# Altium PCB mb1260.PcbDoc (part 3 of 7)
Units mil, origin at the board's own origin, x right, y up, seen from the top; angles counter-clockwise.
Board outline 3189.01 x 3818.89 mil, 6 copper layers (TOP, L2_GND, L3_VCC, L4_SIG, L5_GND, BOTTOM), stack 62.2 mil thick; 308 components, 287 nets, 1220 pads, 851 vias.
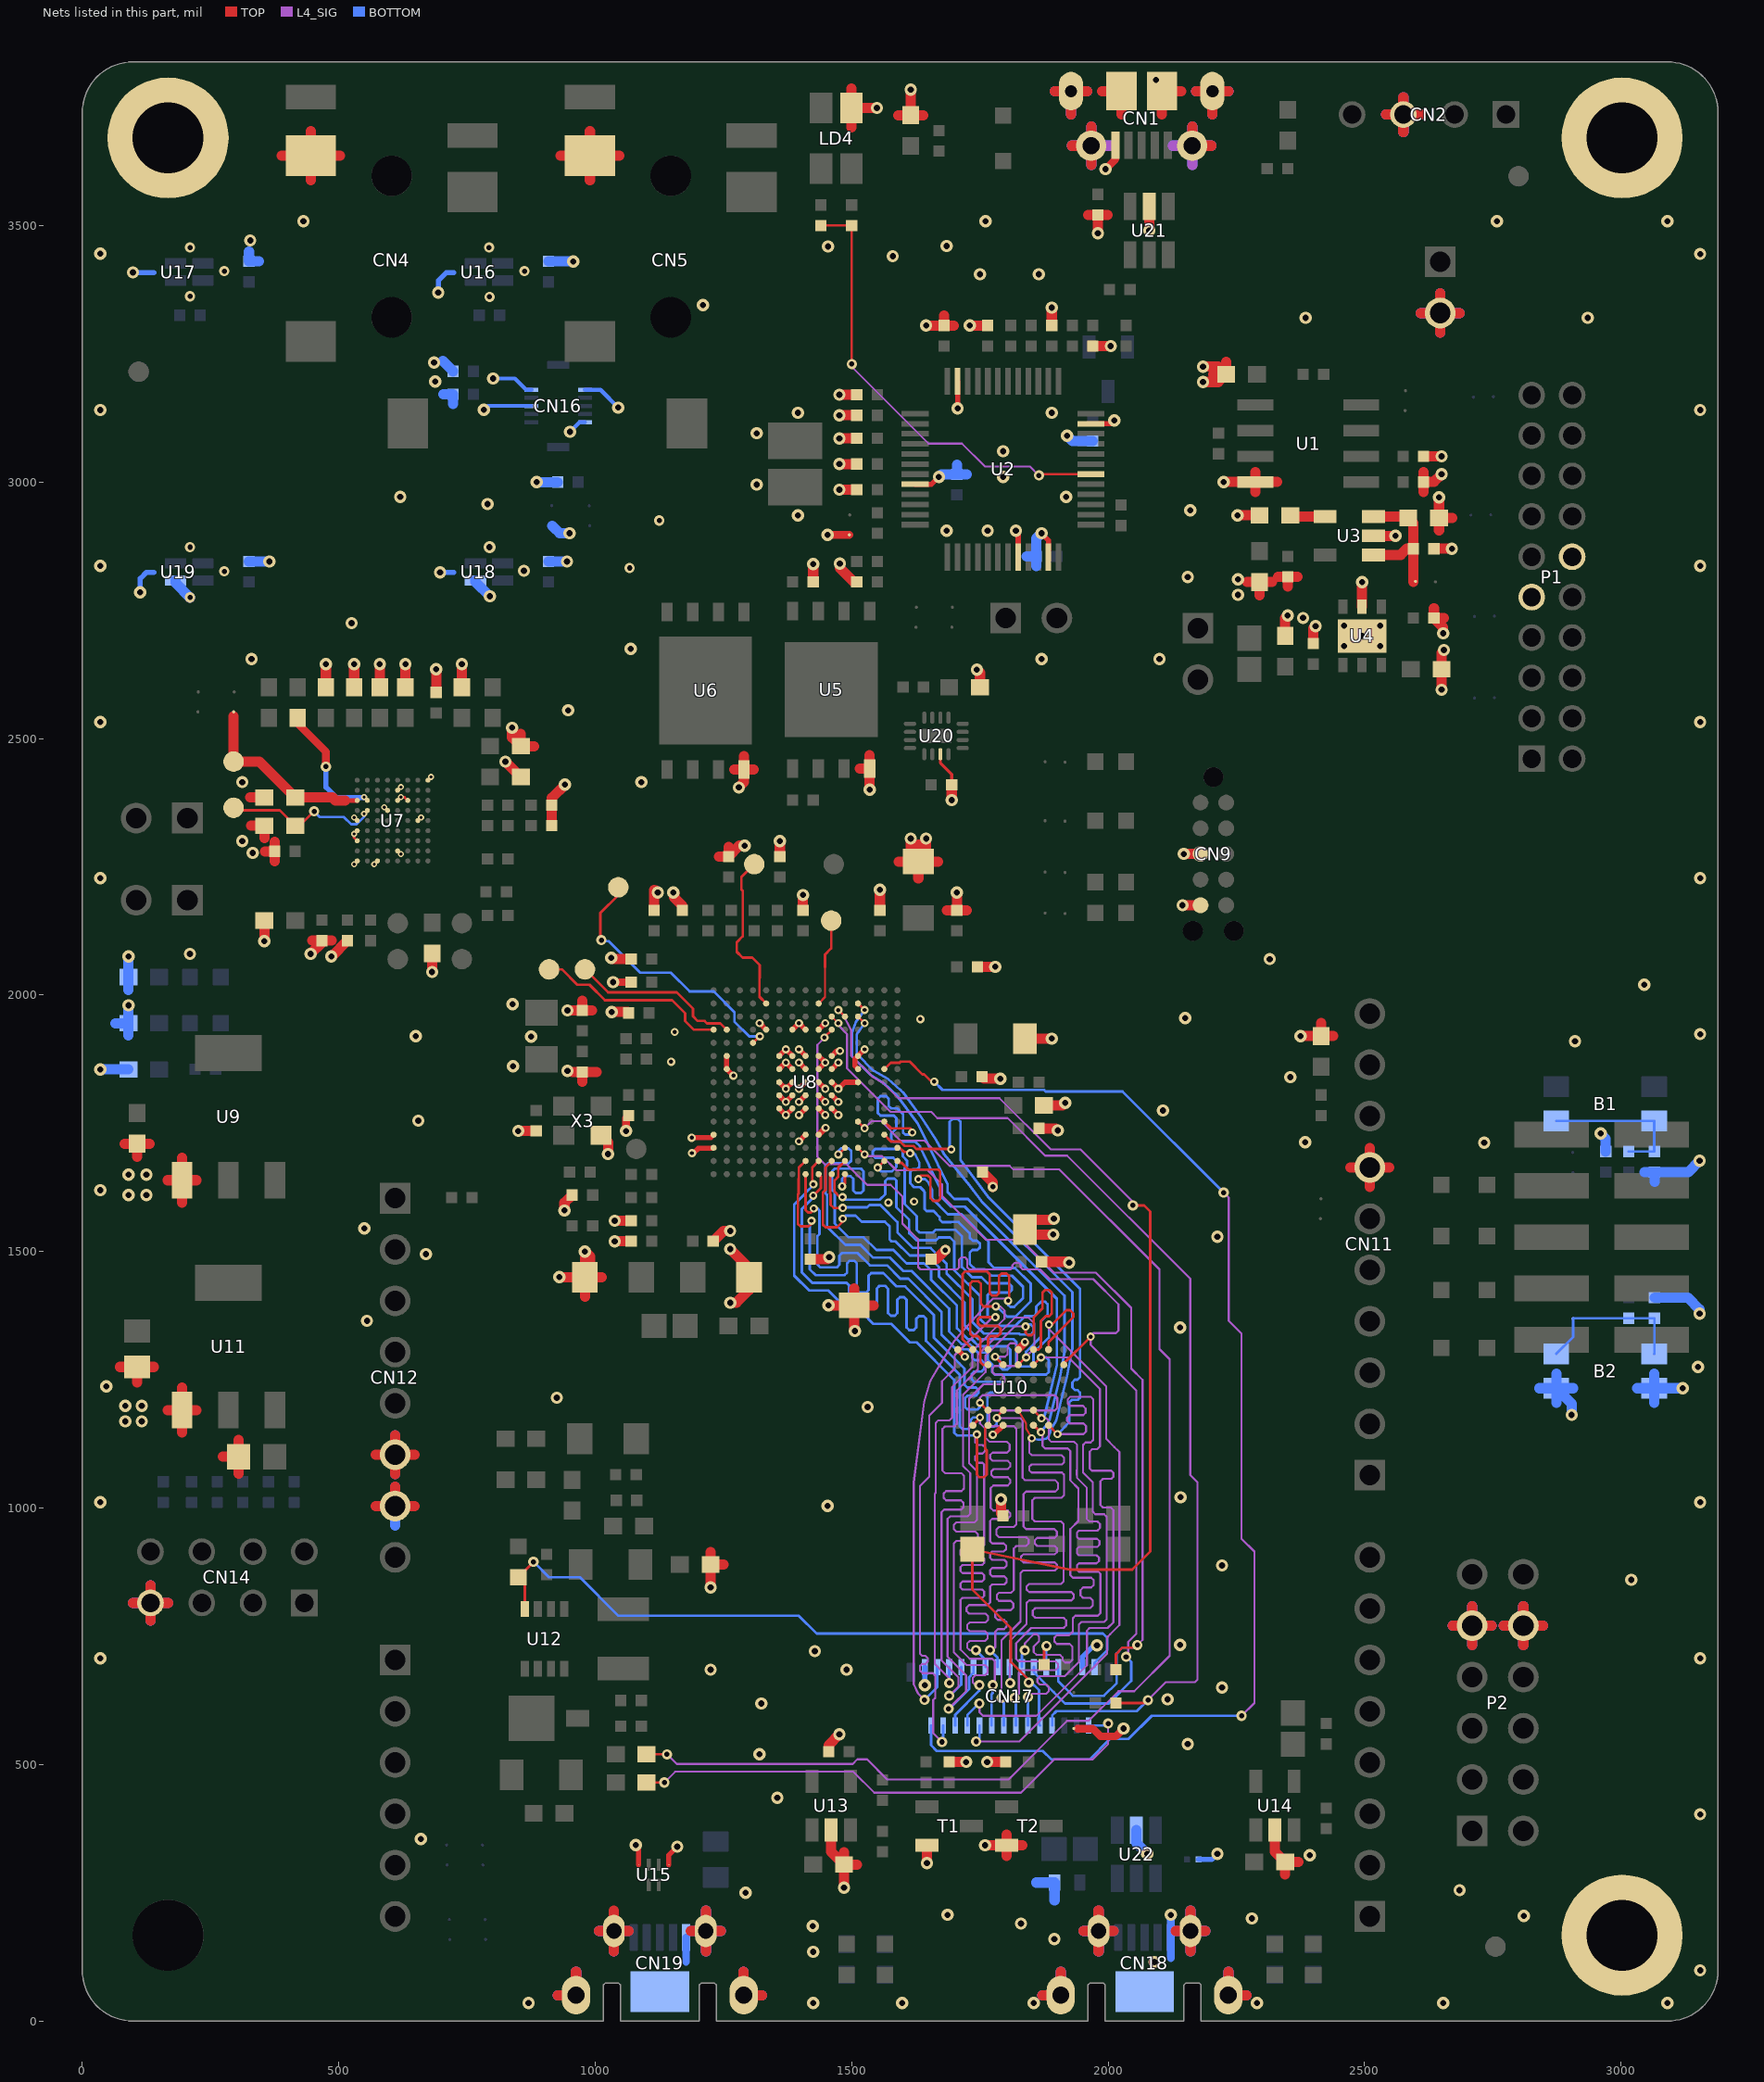
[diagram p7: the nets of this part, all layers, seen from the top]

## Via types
v1: diameter 24, hole 12, TOP to BOTTOM, tented both sides, 389 vias
v2: diameter 20, hole 10, TOP to BOTTOM, tented both sides, 231 vias
v3: diameter 16, hole 8, TOP to BOTTOM, tented both sides, 196 vias
v4: diameter 12, hole 6, TOP to BOTTOM, tented both sides, 35 vias

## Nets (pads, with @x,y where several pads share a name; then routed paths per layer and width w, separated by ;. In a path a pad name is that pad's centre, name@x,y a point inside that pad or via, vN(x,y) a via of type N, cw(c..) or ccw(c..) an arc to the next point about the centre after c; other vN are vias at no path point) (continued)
GND: B2.2 B2.4 C1.2 C2.2 C3.1 C4.1 C5.1 C6.1 C7.1 C8.1 C9.1 C10.1 C11.1 C12.1 C13.1 C14.1 C15.1 C16.1 C17.1 C19.1 C20.2 C21.2 C22.2 C23.2 C24.2 C26.2 C28.2 C29.1 C31.1 C33.2 C34.2 C35.1 C36.1 C37.1 C38.1 C39.1 C40.1 C41.2 C42.2 C43.1 C44.1 C45.1 C46.1 C47.1 C48.1 C49.1 C50.1 C51.1 C52.1 C53.1 C54.2 C55.1 C56.1 C57.1 C58.1 C59.1 C60.1 C61.1 C62.1 C63.1 C64.2 C65.2 C66.2 C68.1 C71.1 C74.1 C77.2 C78.2 C79.2 C80.2 C81.1 C82.1 C83.1 C84.2 C85.2 C86.1 C87.1 C92.2 C93.1 CN1.5 CN1.6 CN1.7 CN1.8 CN1.9 CN1.10 CN1.11 CN2.3 CN3.2 CN4.3 CN5.3 CN9.3 CN9.5 CN11.7 CN12.6 CN12.7 CN14.7 CN16.1 CN16.3 CN16.6 CN16.10 CN17.1 CN17.27 CN18.5 CN18.6 CN18.7 CN18.8 CN18.9 CN18.10 CN19.5 CN19.6 CN19.7 CN19.8 CN19.9 CN19.10 H1.1 H2.1 H4.1 L5.1 LD1.2 LD2.2 LD4.1 LD5.2 LD6.2 P1.5 P1.16 P2.5 P2.11 R3.1 R6.1 R8.1 R9.1 R16.1 R17.1 R18.1 R19.1 R21.1 R22.2 R26.1 R29.1 R31.2 R33.2 R36.1 R37.1 R54.2 R61.1 R75.2 R76.1 R89.1 SB2.2 SB6.1 SB16.1 T1.2 T2.2 U1.4 U2.8 U2.20 U2.23 U2.35 U2.47 U3.2 U4.2 U4.7 U5.4 U6.4 U7.A1 U7.A3 U7.A4 U7.A5 U7.C1 U7.D6 U7.E2 U7.E7 U7.E8 U7.F7 U7.G5 U7.H9 U8.D5 U8.D7 U8.D8 U8.D9 U8.F2 U8.F6 U8.F7 U8.F8 U8.F9 U8.F10 U8.F12 U8.G2 U8.G6 U8.G7 U8.G8 U8.G9 U8.G10 U8.G12 U8.H6 U8.H7 U8.H8 U8.H9 U8.H10 U8.H12 U8.J6 U8.J7 U8.J8 U8.J9 U8.J10 U8.K6 U8.K7 U8.K8 U8.K9 U8.K10 U8.M1 U8.M8 U8.M9 U8.N1 U9.1 U10.D1 U10.E6 U10.H1 U11.1 U13.2 U14.2 U15.5 U15.8 U16.5 U17.5 U18.2 U18.5 U19.2 U19.5 U20.11 U21.2 U22.2 U23.2 U24.2 X3.2 | length 17260.3
  TOP w5: v4(529.8,2254.96) U7.A1@536.1,2261.26 ; v4(529.8,2346.3) U7.A5@536.1,2340 ; U7.A3@536.1,2300.63 529.8,2306.93 v4(529.8,2314.01) U7.A4@536.1,2320.31 ; v4(569.17,2254.96) U7.C1@575.47,2261.26 ; v4(588.86,2365.99) U7.D6@595.16,2359.69 ; U7.E2@614.84,2280.94 v4(621.14,2274.64) ; U7.E7@614.84,2379.37 v4(621.14,2385.68) 628.22,2385.68 U7.F7@634.53,2379.37 ; U7.E8@614.84,2399.06 v4(621.14,2405.36) ; U7.G5@654.21,2340 v4(660.51,2346.3) ; U7.H9@673.9,2418.74 v4(680.2,2425.04)
  TOP w6: U20.11@1672.87,2469.38 1672.87,2452.13 1695,2430 R29.1@1695,2410
  TOP w10: v1(1079,343) 1084.47,337.53 U15.8@1084.47,304.69 ; U15.5@1143.53,304.69 1143.53,323.53 v1(1160,340) ; v3(1188,1721.87) 1225.1,1721.87 U8.M1@1230.87,1727.64 ; v3(1188.63,1691.87) 1191.87,1691.87 1201,1701 1229.82,1701 U8.N1@1230.87,1702.05 ; U8.F2@1256.46,1881.18 U8.G2@1256.46,1855.59 v3(1269.32,1842.73) ; v3(1320.37,1945.22) U8.D5@1333.23,1932.36 ; U8.K6@1358.82,1778.82 1358.82,1778.69 v3(1371.55,1765.96) U8.K7@1384.41,1778.82 ; U8.J6@1358.82,1804.41 1358.82,1804.28 v3(1371.55,1791.55) U8.J7@1384.41,1804.41 ; U8.H6@1358.82,1830 1358.82,1829.87 v3(1371.55,1817.14) U8.H7@1384.41,1830 ; U8.G6@1358.82,1855.59 1358.82,1855.72 v3(1371.55,1868.45) U8.G7@1384.41,1855.59 ; U8.F6@1358.82,1881.18 1358.82,1881.31 v3(1371.55,1894.04) U8.F7@1384.41,1881.18 ; U8.D7@1384.41,1932.36 1384.41,1932.49 v3(1397.14,1945.22) U8.D8@1410,1932.36 ; v3(1397.14,1714.78) U8.M8@1410,1727.64 ; v3(1397.14,1765.96) U8.K8@1410,1778.82 ; v3(1397.14,1791.55) U8.J8@1410,1804.41 ; v3(1397.14,1817.14) U8.H8@1410,1830 ; v3(1397.14,1868.45) U8.G8@1410,1855.59 ; v3(1397.14,1894.04) U8.F8@1410,1881.18 ; U8.K9@1435.59,1778.82 v3(1448.45,1765.96) ; U8.J9@1435.59,1804.41 v3(1448.45,1791.55) ; U8.H9@1435.59,1830 v3(1448.45,1817.14) ; U8.G9@1435.59,1855.59 v3(1448.45,1868.45) 1435.72,1881.18 U8.F9@1435.59,1881.18 ; U8.D9@1435.59,1932.36 v3(1448.32,1945.09) ; U8.K10@1461.18,1778.82 v3(1474.04,1765.96) ; U8.J10@1461.18,1804.41 v3(1474.04,1791.55) ; U8.H10@1461.18,1830 v3(1474.04,1817.14) 1486.9,1830 U8.H12@1512.36,1830 ; U8.G10@1461.18,1855.59 v3(1474.04,1868.45) ; U8.F10@1461.18,1881.18 1471,1891 v3(1477,1891) ; U8.G12@1512.36,1855.59 1512.36,1855.75 1506,1862.11 1506,1874.82 U8.F12@1512.36,1881.18 v3(1525.22,1894.04) ; U2.8@1623.74,2995.47 1655.47,2995.47 v1(1670,3010) ; v1(1706.42,3143.58) U2.47@1706.42,3196.26 ; U10.H1@1706.65,1308.82 v3(1720.62,1294.85) ; v3(1775,1143) 1777.06,1143 U10.E6@1795.24,1161.18 ; v1(1820,2905) 1824.53,2900.47 U2.20@1824.53,2853.74 ; v1(1870,2900) 1883.58,2886.42 U2.23@1883.58,2853.74 ; U2.35@1966.26,3113.58 2005.74,3113.58 v1(2012.16,3120)
  TOP w12: U8.M9@1435.59,1727.64 1435.75,1727.64 v3(1449.1,1740.99)
  TOP w15: v1(1035,2025) C46.1@1070,2025 ; v1(1059.97,1735) 1059.97,1759.97 C53.1@1065,1765 ; v1(1453.01,2896.99) SB6.1@1495.33,2896.99 ; U10.D1@1824.76,1308.82 1837.6,1321.66 v3(1837.6,1323.6) ; 1940,570 1970,570 ; 1970,570.33 1970,570 ; v1(1995,3610) 2014.17,3629.17 CN1.5@2014.17,3656.49 ; v1(2030,570.33) 2014.67,555 1985,555 1970,570
  TOP w20: 73.78,1275 C68.1@106.8,1275 ; 82.78,1710 C57.1@106.8,1710 ; 98.97,815 CN14.7@132.99,815 ; 106.8,1244.48 C68.1@106.8,1275 ; 106.8,1684.48 C57.1@106.8,1710 ; 130.82,1710 C57.1@106.8,1710 ; 132.99,780.98 CN14.7@132.99,815 ; 132.99,849.02 CN14.7@132.99,815 ; 139.82,1275 C68.1@106.8,1275 ; 166.43,1190.98 U11.1@194.45,1190.98 ; 166.43,1638.98 U9.1@194.45,1638.98 ; 167.01,815 CN14.7@132.99,815 ; 194.45,1147.46 U11.1@194.45,1190.98 ; 194.45,1234.5 U11.1@194.45,1190.98 ; 194.45,1595.46 U9.1@194.45,1638.98 ; 194.45,1682.5 U9.1@194.45,1638.98 ; 222.47,1190.98 U11.1@194.45,1190.98 ; 222.47,1638.98 U9.1@194.45,1638.98 ; 274.48,1100 C74.1@305,1100 ; 305,1066.98 C74.1@305,1100 ; 305,1133.02 C74.1@305,1100 ; 327,2385 C29.1@355,2385 ; 329.48,2330 C31.1@355,2330 355,2305.98 ; v1(355,2105) C35.1@355,2145 ; 355.98,2280 C33.2@375,2280 ; 375,2260.98 C33.2@375,2280 ; 375,2299.02 C33.2@375,2280 ; 388.65,3635.98 CN4.3@445.67,3635.98 ; v1(445,2080) 467,2102 C41.2@467,2106 ; 445.67,3588.46 CN4.3@445.67,3635.98 ; 445.67,3683.5 CN4.3@445.67,3635.98 ; 447.98,2106 C41.2@467,2106 ; C19.1@475,2600 v1(475,2645) ; v1(485.5,2075) 486,2075 C42.2@517,2106 ; 486.02,2106 C41.2@467,2106 ; 502.69,3635.98 CN4.3@445.67,3635.98 ; C20.2@530,2600 v1(530,2645) ; 571.82,1003.94 CN12.7@609.84,1003.94 ; 571.82,1103.94 CN12.6@609.84,1103.94 ; C21.2@580,2600 v1(580,2645) ; 609.84,1041.96 CN12.7@609.84,1003.94 ; 609.84,1065.92 CN12.6@609.84,1103.94 ; 609.84,1141.96 CN12.6@609.84,1103.94 ; C22.2@630,2600 v1(630,2645) ; 647.86,1003.94 CN12.7@609.84,1003.94 ; 647.86,1103.94 CN12.6@609.84,1103.94 ; v1(682,2045) C43.1@682,2081 ; C23.2@690,2590 v1(690,2635) ; C24.2@740,2600 v1(740,2645) ; v1(825,2455) C28.2@855,2425 ; v1(838,2521) 838,2502 C26.2@855,2485 ; v1(850,1735) C55.1@885,1735 ; 855,2509.02 C26.2@855,2485 ; 880.52,2485 C26.2@855,2485 ; R33.2@915,2330 R31.2@915,2370 915,2384 v1(941,2410) ; 927.07,50.4 CN19.9@962.59,50.4 962.59,95.92 ; v1(930,1450) C64.2@980,1450 ; 932.66,3635.98 CN5.3@989.68,3635.98 ; v1(940,1580) 940,1595 C93.1@955,1610 ; v1(946,1970) C48.1@975,1970 ; v1@955.98,1850 C51.1@975,1850 ; 975,1830.98 C51.1@975,1850 ; 975,1989.02 C48.1@975,1970 ; 980,1411.98 C64.2@980,1450 ; v1@980,1488.02 C64.2@980,1450 ; v1(980,1500) 990,1490 990,1460 C64.2@980,1450 ; 989.68,3588.46 CN5.3@989.68,3635.98 ; 989.68,3683.5 CN5.3@989.68,3635.98 ; 994.02,1970 C48.1@975,1970 ; 1003,1850 C51.1@975,1850 ; 1007.39,175.6 CN19.6@1036.41,175.6 ; X3.2@1011.42,1726.46 1025,1712.88 v1(1025,1690) ; 1013.02,1450 C64.2@980,1450 ; v1(1030.96,2072.48) 1031.98,2072.48 1034.46,2070 C44.1@1070,2070 ; v1(1031.98,1967) 1063,1967 C47.1@1065,1965 ; 1036.41,136.08 CN19.6@1036.41,175.6 ; 1036.41,215.12 CN19.6@1036.41,175.6 ; v1(1038,1520) C59.1@1070,1520 ; v1(1038,1560) R61.1@1070,1560 ; 1046.7,3635.98 CN5.3@989.68,3635.98 ; 1065.43,175.6 CN19.6@1036.41,175.6 ; C36.1@1115,2165 1115,2204.41 1115.9,2203.51 1118.49,2203.51 v1(1122,2200) ; v1(1152,2200) 1154,2198 1154,2190 1170,2174 C37.1@1170,2165 ; 1186.53,175.6 CN19.7@1215.55,175.6 ; 1215.55,136.08 CN19.7@1215.55,175.6 ; 1215.55,215.12 CN19.7@1215.55,175.6 ; v1(1225,845) L5.1@1225,890 ; 1225,914.02 L5.1@1225,890 ; C60.1@1230,1520 1250,1540 v1(1263,1540) ; 1240.98,2270 R36.1@1260,2270 ; 1244.57,175.6 CN19.7@1215.55,175.6 ; 1250.52,890 L5.1@1225,890 ; 1260,2289.02 R36.1@1260,2270 ; v1(1263,1505) 1300,1468 C65.2@1300,1450 1300,1425 1275,1400 v1(1263.5,1400) ; 1270.98,2439.76 U6.4@1290,2439.76 ; v1(1280,2404.5) 1280,2405 1290,2415 U6.4@1290,2439.76 ; 1289.37,95.92 CN19.8@1289.37,50.4 1324.89,50.4 ; 1290,2465.78 U6.4@1290,2439.76 ; v1(1291.55,2291.08) 1291.47,2291.08 1291.47,2291.16 1291.31,2291.31 1281.31,2291.31 R36.1@1260,2270 ; 1309.02,2439.76 U6.4@1290,2439.76 ; R37.1@1360,2270 v1(1360,2300) ; C38.1@1405,2165 v1(1405,2195) ; C61.1@1419,1485 1452,1485 v1(1456.01,1489.01) ; C13.1@1425,2805 v1(1425,2840) ; R16.1@1455,525 1455,538 v1(1476,559) ; v1(1455,1395) C66.2@1505,1395 ; U13.2@1460,372.76 1460,330 C78.2@1485,305 ; v1(1476,2985) C7.1@1510,2985 ; v1(1476,3035) C6.1@1510,3035 ; v1(1476,3085) C4.1@1510,3085 ; v1(1476,3130) R19.1@1510,3130 ; v1(1476,3170) R17.1@1510,3170 ; v1(1477,2841) 1477,2832 1504,2805 R26.1@1510,2805 ; v1(1485,260) C78.2@1485,305 ; 1485,329.02 C78.2@1485,305 ; 1499.53,3691.54 LD4.1@1499.53,3729.06 ; 1499.53,3766.58 LD4.1@1499.53,3729.06 ; 1505,1428.02 C66.2@1505,1395 ; v1(1506,1345) 1506,1349 1505,1350 C66.2@1505,1395 ; 1510.52,305 C78.2@1485,305 ; 1515.98,2441.46 U5.4@1535,2441.46 ; v1(1535,2400) U5.4@1535,2441.46 ; 1535,2467.48 U5.4@1535,2441.46 ; 1543.02,1395 C66.2@1505,1395 ; v1(1549.06,3729.06) LD4.1@1499.53,3729.06 ; C39.1@1555,2165 v1(1555,2205) ; 1590.98,3715 LD2.2@1615,3715 ; 1591.98,2260 C34.2@1630,2260 ; v1(1615,2305) 1615,2275 C34.2@1630,2260 ; v1(1615,3765) LD2.2@1615,3715 ; 1630,2226.98 C34.2@1630,2260 ; 1630,2293.02 C34.2@1630,2260 ; 1639.02,3715 LD2.2@1615,3715 ; v1(1645,2305) 1645,2275 C34.2@1630,2260 ; v1(1645,3305) C1.2@1680,3305 ; v1(1646.69,308) T1.2@1646.69,342.6 ; C62.1@1655,1485 1665,1485 1683,1503 v2(1682.5,1503) ; 1668.02,2260 C34.2@1630,2260 ; 1680,3324.02 C1.2@1680,3305 ; 1685.98,2165 C40.1@1705,2165 ; R75.2@1690,505 v1(1723.28,505) ; v1(1695,2380) R29.1@1695,2410 ; 1699.02,3305 C1.2@1680,3305 ; v1(1705,2200) C40.1@1705,2165 ; 1724.02,2165 C40.1@1705,2165 ; v1(1730,3305) R3.1@1765,3305 ; v1(1744,2634) 1750,2628 C92.2@1750,2600 ; C45.1@1745,2055 v1(1780,2055) ; C56.1@1755,1655 1775,1635 v2(1775,1626) ; C52.1@1758.01,1836.99 v1(1790.01,1837) ; v1(1760,342.6) T2.2@1801.69,342.6 ; v1(1764,505) R76.1@1800,505 ; v1(1791,1017) 1791,989 C71.1@1795,985 ; 1801.69,322.08 T2.2@1801.69,342.6 ; 1801.69,363.12 T2.2@1801.69,342.6 ; 1832.21,342.6 T2.2@1801.69,342.6 ; C49.1@1838,1915 v1(1890,1915) ; R54.2@1865,1740 1898,1740 v1(1902,1736) ; C63.1@1870,1480 1922,1480 v1(1924,1478) ; 1871.96,50.4 CN18.9@1907.48,50.4 1907.48,95.92 ; C54.2@1875,1785 1911,1785 v1(1916,1790) ; R6.1@1890,3305 v1(1890,3340) ; v1(1893,1533) 1848,1533 C58.1@1838,1543 1838,1548 1852,1562 1892,1562 v1(1894,1564) ; 1896.03,3761.8 CN1.7@1927.55,3761.8 ; 1927.55,3716.28 CN1.7@1927.55,3761.8 ; 1929.4,3655.5 CN1.9@1966.92,3655.5 ; 1952.28,175.6 CN18.6@1981.3,175.6 ; 1959.07,3761.8 CN1.7@1927.55,3761.8 ; 1960.98,3520.59 R9.1@1980,3520.59 ; 1966.92,3617.98 CN1.9@1966.92,3655.5 ; 1966.92,3693.02 CN1.9@1966.92,3655.5 ; R8.1@1970,3265 v1(2005,3265) ; v1(1980,3485) R9.1@1980,3520.59 ; 1981.3,136.08 CN18.6@1981.3,175.6 ; 1981.3,215.12 CN18.6@1981.3,175.6 ; 1988.46,3761.8 CN1.11@2025.98,3761.8 2025.98,3716.28 ; 1999.02,3520.59 R9.1@1980,3520.59 ; 2010.32,175.6 CN18.6@1981.3,175.6 ; v1(2080,3490) U21.2@2080,3537.24 ; 2104.72,3716.28 CN1.10@2104.72,3761.8 2142.24,3761.8 ; 2131.42,175.6 CN18.7@2160.44,175.6 ; v1(2145,2175) CN9.5@2180,2175 ; v1(2147.5,2275) CN9.3@2180,2275 ; 2160.44,136.08 CN18.7@2160.44,175.6 ; 2160.44,215.12 CN18.7@2160.44,175.6 ; 2163.78,3693.02 CN1.8@2163.78,3655.5 2201.3,3655.5 ; 2171.63,3761.8 CN1.6@2203.15,3761.8 ; v1(2185,3195) 2215,3195 C3.1@2230,3210 ; v1(2185,3225) 2215,3225 C3.1@2230,3210 ; 2189.46,175.6 CN18.7@2160.44,175.6 ; 2203.15,3716.28 CN1.6@2203.15,3761.8 ; 2204.48,3210 C3.1@2230,3210 ; v1(2225,3000) U1.4@2286.7,3000 ; 2230,3234.02 C3.1@2230,3210 ; 2234.26,95.92 CN18.8@2234.26,50.4 2269.78,50.4 ; 2234.67,3761.8 CN1.6@2203.15,3761.8 ; v1(2252,2935) C8.1@2295,2935 ; 2270.98,2805 C11.1@2295,2805 ; 2286.7,2980.98 U1.4@2286.7,3000 ; 2286.7,3019.02 U1.4@2286.7,3000 ; 2295,2779.48 C11.1@2295,2805 ; 2319.02,2805 C11.1@2295,2805 ; U14.2@2325,372.76 2325,330 C77.2@2345,310 ; 2329.72,3000 U1.4@2286.7,3000 ; 2330.98,2815 C12.1@2350,2815 ; 2345,285.98 C77.2@2345,310 ; C15.1@2345,2700 2345,2735 v1(2350,2740) ; 2350,2795.98 C12.1@2350,2815 ; 2369.02,2815 C12.1@2350,2815 ; 2370.52,310 C77.2@2345,310 ; v1(2375,1920) C50.1@2415,1920 ; C16.1@2400,2685 2400,2714.85 v1(2404.3,2719.15) ; 2415,1945.52 C50.1@2415,1920 ; 2439.02,1920 C50.1@2415,1920 ; 2471.82,1663.94 CN11.7@2509.84,1663.94 ; U4.2@2495,2756.52 v1(2495,2805) ; 2509.84,1625.92 CN11.7@2509.84,1663.94 ; 2509.84,1701.96 CN11.7@2509.84,1663.94 ; U3.2@2517.24,2895 v1(2560,2895) ; 2541.39,3716.23 CN2.3@2575.41,3716.23 ; 2547.86,1663.94 CN11.7@2509.84,1663.94 ; 2575.41,3682.21 CN2.3@2575.41,3716.23 ; 2575.41,3750.25 CN2.3@2575.41,3716.23 ; 2609.18,3329.41 CN3.2@2647.2,3329.41 ; 2609.43,3716.23 CN2.3@2575.41,3716.23 ; 2615,2980.98 R22.2@2615,3000 ; 2615,3019.02 R22.2@2615,3000 ; C5.1@2615,3050 v1(2650,3050) ; 2635,2754.02 C14.1@2635,2735 ; C10.1@2635,2870 v1(2670,2870) ; 2645,2905.98 C9.1@2645,2930 ; v1(2645,2970) C9.1@2645,2930 ; 2647.2,3291.39 CN3.2@2647.2,3329.41 ; 2647.2,3367.43 CN3.2@2647.2,3329.41 ; v1(2650,2595) C17.1@2650,2635 2650,2667 2654.53,2671.53 v1(2654.53,2672.65) ; v1(2650,3015) 2635,3000 R22.2@2615,3000 ; v1(2653,2705) 2653,2717 C14.1@2635,2735 ; 2654.02,2735 C14.1@2635,2735 ; 2670.52,2930 C9.1@2645,2930 ; 2671.31,770.63 P2.5@2709.33,770.63 ; 2685.22,3329.41 CN3.2@2647.2,3329.41 ; 2709.33,732.61 P2.5@2709.33,770.63 ; 2709.33,808.65 P2.5@2709.33,770.63 ; 2747.35,770.63 P2.5@2709.33,770.63 ; 2771.31,770.63 P2.11@2809.33,770.63 ; 2809.33,732.61 P2.11@2809.33,770.63 ; 2809.33,808.65 P2.11@2809.33,770.63 ; 2847.35,770.63 P2.11@2809.33,770.63
  L4_SIG w20: 98.97,815 CN14.7@132.99,815 ; 132.99,780.98 CN14.7@132.99,815 ; 132.99,849.02 CN14.7@132.99,815 ; 167.01,815 CN14.7@132.99,815 ; 927.07,50.4 CN19.9@962.59,50.4 962.59,95.92 ; 1007.39,175.6 CN19.6@1036.41,175.6 ; 1036.41,136.08 CN19.6@1036.41,175.6 ; 1065.43,175.6 CN19.6@1036.41,175.6 ; 1186.53,175.6 CN19.7@1215.55,175.6 ; 1215.55,136.08 CN19.7@1215.55,175.6 ; 1215.55,215.12 CN19.7@1215.55,175.6 ; 1244.57,175.6 CN19.7@1215.55,175.6 ; 1289.37,95.92 CN19.8@1289.37,50.4 1324.89,50.4 ; 1871.96,50.4 CN18.9@1907.48,50.4 1907.48,95.92 ; 1896.03,3761.8 CN1.7@1927.55,3761.8 ; 1927.55,3716.28 CN1.7@1927.55,3761.8 ; 1929.4,3655.5 CN1.9@1966.92,3655.5 ; 1952.28,175.6 CN18.6@1981.3,175.6 ; 1959.07,3761.8 CN1.7@1927.55,3761.8 ; 1966.92,3617.98 CN1.9@1966.92,3655.5 ; 1966.92,3693.02 CN1.9@1966.92,3655.5 ; 1981.3,136.08 CN18.6@1981.3,175.6 ; 1981.3,215.12 CN18.6@1981.3,175.6 ; 2004.44,3655.5 CN1.9@1966.92,3655.5 ; 2010.32,175.6 CN18.6@1981.3,175.6 ; 2126.26,3655.5 CN1.8@2163.78,3655.5 ; 2131.42,175.6 CN18.7@2160.44,175.6 ; 2160.44,136.08 CN18.7@2160.44,175.6 ; 2160.44,215.12 CN18.7@2160.44,175.6 ; 2163.78,3617.98 CN1.8@2163.78,3655.5 ; 2163.78,3693.02 CN1.8@2163.78,3655.5 ; 2171.63,3761.8 CN1.6@2203.15,3761.8 ; 2189.46,175.6 CN18.7@2160.44,175.6 ; 2201.3,3655.5 CN1.8@2163.78,3655.5 ; 2203.15,3716.28 CN1.6@2203.15,3761.8 ; 2234.26,95.92 CN18.8@2234.26,50.4 2269.78,50.4 ; 2234.67,3761.8 CN1.6@2203.15,3761.8 ; 2541.39,3716.23 CN2.3@2575.41,3716.23 ; 2575.41,3682.21 CN2.3@2575.41,3716.23 ; 2609.18,3329.41 CN3.2@2647.2,3329.41 ; 2609.43,3716.23 CN2.3@2575.41,3716.23 ; 2647.2,3291.39 CN3.2@2647.2,3329.41 ; 2647.2,3367.43 CN3.2@2647.2,3329.41 ; 2671.31,770.63 P2.5@2709.33,770.63 ; 2685.22,3329.41 CN3.2@2647.2,3329.41 ; 2709.33,808.65 P2.5@2709.33,770.63 ; 2747.35,770.63 P2.5@2709.33,770.63 ; 2771.31,770.63 P2.11@2809.33,770.63 ; 2809.33,808.65 P2.11@2809.33,770.63 ; 2847.35,770.63 P2.11@2809.33,770.63
  BOTTOM w7: v1(782.84,3140.76) 790.24,3148.16 CN16.3@875.57,3148.16
  BOTTOM w8: v1(800.84,3201.76) 843.24,3201.76 865.34,3179.66 CN16.1@875.57,3179.66 ; v1(950.84,3097.76) 969.74,3116.66 CN16.6@979.91,3116.66 ; CN16.10@979.91,3179.66 1010.34,3179.66 v1(1045,3145)
  BOTTOM w10: v1(98.87,3408.41) U17.5@139.46,3408.41 ; v1(113,2785) 113,2811.8 125,2823.8 U19.5@139.46,2823.8 ; v1(694,3369) 694,3392.41 710,3408.41 U16.5@724.07,3408.41 ; v1(697.61,2823.8) U18.5@724.07,2823.8 ; v1(1642.8,654.8) CN17.1@1642.8,690.09 ; CN17.27@1949.88,690.09 1949.88,709.88 1972.5,732.5 v1(1978.19,732.5) ; U23.2@2176.02,315 2202,315 v1(2213,326)
  BOTTOM w15: 1177.16,115.31 CN19.5@1177.16,162.8 ; v1(2122,207) 2122.05,206.95 CN18.5@2122.05,162.8 2122.05,122.95
  BOTTOM w20: v1(35,1855) LD1.2@90,1855 ; 64.48,1945 LD6.2@90,1945 ; 90,1920.98 LD6.2@90,1945 ; v1(90,1980) LD6.2@90,1945 ; 90,2010 LD5.2@90,2035 v1(90,2075) ; 98.97,815 CN14.7@132.99,815 ; 132.99,780.98 CN14.7@132.99,815 ; 132.99,849.02 CN14.7@132.99,815 ; U19.2@181.89,2808.07 181.89,2803.11 v2(210,2775) ; C85.2@325,2845 v1(365,2845) ; 325,3449.02 C80.2@325,3430 344.02,3430 ; 609.84,965.92 CN12.7@609.84,1003.94 609.84,1041.96 ; 609.84,1065.92 CN12.6@609.84,1103.94 609.84,1141.96 ; 702.84,3235.76 C2.2@722.84,3215.76 ; 703.82,3170.76 R21.1@722.84,3170.76 722.84,3151.74 ; U18.2@766.5,2808.07 766.5,2805.5 v1(794.61,2777.39) ; v1(885.84,2999.76) R18.1@926.84,2999.76 ; C84.2@908.74,2845 v1(945,2845) ; C79.2@908.74,3430 v1(957,3430) ; SB2.2@916.03,2914.93 918.86,2912.1 930.96,2900 v1(950,2900) ; 927.07,50.4 CN19.9@962.59,50.4 962.59,95.92 ; 1007.39,175.6 CN19.6@1036.41,175.6 1036.41,136.08 ; 1215.55,136.08 CN19.7@1215.55,175.6 ; 1215.55,215.12 CN19.7@1215.55,175.6 ; 1244.57,175.6 CN19.7@1215.55,175.6 ; 1289.37,95.92 CN19.8@1289.37,50.4 1324.89,50.4 ; v1(1670,3010) 1675,3015 C82.1@1705,3015 ; 1705,3034.02 C82.1@1705,3015 ; 1724.02,3015 C82.1@1705,3015 ; 1840.98,2855 C83.1@1860,2855 ; 1860,270 U24.2@1895.39,270 1895.39,235.39 ; 1860,2835.98 C83.1@1860,2855 ; v1(1870,2900) 1860,2890 C83.1@1860,2855 ; 1871.96,50.4 CN18.9@1907.48,50.4 1907.48,95.92 ; 1896.03,3761.8 CN1.7@1927.55,3761.8 ; v1(1920,3090) 1930,3080 C81.1@1970,3080 ; 1927.55,3716.28 CN1.7@1927.55,3761.8 ; 1929.4,3655.5 CN1.9@1966.92,3655.5 ; 1952.28,175.6 CN18.6@1981.3,175.6 1981.3,136.08 ; 1959.07,3761.8 CN1.7@1927.55,3761.8 ; 1966.92,3617.98 CN1.9@1966.92,3655.5 ; 1966.92,3693.02 CN1.9@1966.92,3655.5 ; 2004.44,3655.5 CN1.9@1966.92,3655.5 ; U22.2@2055,372.24 2055,347 v1(2076,326) ; 2126.26,3655.5 CN1.8@2163.78,3655.5 ; 2160.44,136.08 CN18.7@2160.44,175.6 ; 2160.44,215.12 CN18.7@2160.44,175.6 ; 2163.78,3617.98 CN1.8@2163.78,3655.5 ; 2163.78,3693.02 CN1.8@2163.78,3655.5 ; 2171.63,3761.8 CN1.6@2203.15,3761.8 ; 2189.46,175.6 CN18.7@2160.44,175.6 ; 2201.3,3655.5 CN1.8@2163.78,3655.5 ; 2203.15,3716.28 CN1.6@2203.15,3761.8 ; 2234.26,95.92 CN18.8@2234.26,50.4 2269.78,50.4 ; 2234.67,3761.8 CN1.6@2203.15,3761.8 ; 2541.39,3716.23 CN2.3@2575.41,3716.23 ; 2575.41,3682.21 CN2.3@2575.41,3716.23 ; 2575.41,3750.25 CN2.3@2575.41,3716.23 ; 2609.18,3329.41 CN3.2@2647.2,3329.41 ; 2609.43,3716.23 CN2.3@2575.41,3716.23 ; 2647.2,3367.43 CN3.2@2647.2,3329.41 ; 2671.31,770.63 P2.5@2709.33,770.63 ; 2685.22,3329.41 CN3.2@2647.2,3329.41 ; 2709.33,732.61 P2.5@2709.33,770.63 ; 2709.33,808.65 P2.5@2709.33,770.63 ; 2747.35,770.63 P2.5@2709.33,770.63 ; 2771.31,770.63 P2.11@2809.33,770.63 ; 2809.33,732.61 P2.11@2809.33,770.63 ; 2809.33,808.65 P2.11@2809.33,770.63 ; 2840.51,1233.54 B2.2@2873.53,1233.54 ; 2847.35,770.63 P2.11@2809.33,770.63 ; 2873.53,1205.52 B2.2@2873.53,1233.54 ; 2873.53,1261.56 B2.2@2873.53,1233.54 ; v1(2903.53,1181.47) 2903.53,1203.54 B2.2@2873.53,1233.54 ; 2906.55,1233.54 B2.2@2873.53,1233.54 ; v1(2960,1730) 2970,1720 C86.1@2970,1695 ; 3031.45,1233.54 B2.4@3064.47,1233.54 ; 3045.98,1655 R89.1@3065,1655 ; 3064.47,1205.52 B2.4@3064.47,1233.54 ; 3064.47,1261.56 B2.4@3064.47,1233.54 ; C87.1@3065,1410 3130,1410 3153,1387 v1(3153,1379) ; 3065,1635.98 R89.1@3065,1655 ; v1(3120,1233.54) B2.4@3064.47,1233.54 ; v1(3153,1677) 3131,1655 R89.1@3065,1655
  other v1: 870,35 1425,35 1598.43,35 1855,35 2290,35 2653.15,35 3090.19,35 3154.01,98.82 2090,115 1425,135 1895,160 1424,185 1830,190 2280,200 2810,205 1687,207 1293,250 2685,255 2393,323 660,355 3154.01,402.97 1355,435 1320,520 2155,540 1324,619 2116,627 2222,650 1225,685 1490,685 35,707.12 3154.01,707.12 1428,721 2140,733 3020,860 2222,888 1453,1004 35,1011.27 3154.01,1011.27 2141,1021 84,1169 116,1169 1531,1197 84,1199 116,1199 925,1215 47,1237 3150,1275 2140,1352 555,1365 670,1495 2213,1529 550,1545 90,1610 125,1610 35,1619.57 90,1650 125,1650 2733,1712 2384,1713 655,1755 2107,1775 2355,1840 946,1852 840,1861 2910,1910 875,1919 650,1920 3154.01,1923.73 2150,1955 839,1982 3045,2020 2315,2070 210,2080 35,2227.88 3154.01,2227.88 332,2277 312,2300 312,2415 1090,2415 35,2532.03 3154.01,2532.03 947,2555 330,2655 1870,2655 2100,2655 1069,2675 2460,2680 2530,2680 2495,2700 2460,2720 2530,2720 525,2725 2380,2735 2253,2780 2253,2810 2155,2815 861,2827 35,2836.18 3154.01,2836.18 794,2873 1685,2905 1765,2905 1395,2935 2160,2945 790.14,2957.06 620,2971 1918,2971 1315,2995 1795,3010 1795,3060 1315,3095 1395,3135 1890,3135 35,3140.33 3154.01,3140.33 687.84,3195.76 685.85,3233.08 2385,3320 2935,3320 1210,3345 1750,3405 1865,3405 1580,3440 3154.01,3444.48 35,3445 1454.06,3459.06 1685,3460 327.42,3470.9 431.19,3508.3 1760.69,3508.3 2757.82,3508.3 3090.19,3508.3 2093.07,3783.89
  other v2: 277,2826 1067,2832.39 210,2873 1125,2925 794,3361 210,3362 277,3411 862,3411 210,3457 793,3457
  other v3: 1571.48,1595.47 1621.44,1597.54 1148,1870 1155,1928 1633.82,1953
LCD-RS_A0: CN17.21 R101.2 | length 79.4
  TOP w5: R101.2@1875,695 1875,726 v2(1880,731)
  BOTTOM w5: CN17.21@1879.02,690.09 1879.02,730.02 v2(1880,731)
LCD_BL: L7.1 U8.L12 | length 2627.5
  TOP w5: L7.1@1100,520 v2(1140,520) ; U8.L12@1512.36,1753.23 v3(1525.22,1740.37)
  L4_SIG w4: v2(1140,520) 1159,501 1502,501 1511,510 1530,510 1569,471 1806,471 1920,585 1961.98,585 2019.98,643 2051.02,643 2120,711.98 2120,1290 2100,1310 2100,1465 1905,1660 1815,1660 1808,1667 1690.83,1667 1641.83,1716 1594.98,1716 1556.61,1754.37 1539.22,1754.37 v3(1525.22,1740.37)
LCD_NE: CN17.22 R70.2 U8.C10 | length 2137
  TOP w4: U8.C10@1461.14,1957.9 v3(1473.97,1945.07)
  TOP w5: R70.2@2015,620 2071.88,620 v2(2077.48,625.6)
  L4_SIG w4: v3(1473.97,1945.07) 1474.04,1945 1474.04,1941 1491,1924.04 1491,1857 1576,1772 1655,1772 1667,1760 1804,1760 1877,1687 1920,1687 2160,1447 2160,1064 2174,1050 2174,665.47 2169,660.47 2111.96,660.47 2077.29,625.79 2077.09,625.6 v2(2077.48,625.6)
  BOTTOM w5: CN17.22@1890.83,575.91 1890.83,595.83 1899,604 2055.88,604 v2(2077.48,625.6)
LCD_PSRAM_D0: CN17.18 U8.M14 U10.B6 | length 2098.1
  TOP w5: U8.M14@1563.54,1727.64 1576.63,1714.55 1594.31,1714.55 1601.86,1707 1602.26,1707 1603.27,1706 1620.01,1706 1626.01,1700 1693,1700 v3(1694,1699) ; U10.B6@1883.82,1161.18 v3(1901,1144)
  L4_SIG w4: v2(1843.58,631.95) 1843.58,633 1848.58,638 1879,638 1884,643 1884,651 1879,656 1866.69,656 1862,660.69 1862,667.31 1866.69,672 1915,672 1943,700 1943,773 1948,778 1992,778 1997,783 1997,983 1992,988 1975,988 1970,993 1970,1050 1951,1069 1951,1123 1956,1128 1966,1128 1971,1133 1971,1212 1966,1217 1926,1217 1921,1212 1921,1204 1926,1199 1951,1199 1956,1194 1956,1185.69 1951.31,1181 1924.69,1181 1920,1176.31 1920,1169.69 1924.69,1165 1952,1165 1957,1160 1957,1149 1952,1144 v3(1901,1144)
  BOTTOM w5: v3(1694,1699) 1691,1702 1691,1753 1696,1758 1707,1758 1712,1753 1712,1678 1766.29,1606.3 1945,1427.59 1945,1255 1940,1250 1935,1250 1930,1245 1930,1235 1935,1230 1940,1230 1945,1225 1945,1215 1941,1211 1929,1211 1924,1206 1924,1167 v3(1901,1144) ; CN17.18@1843.58,575.91 v2(1843.58,631.95)
LCD_PSRAM_D1: CN17.17 U8.L14 U10.C5 | length 2157.7
  TOP w5: U8.L14@1563.54,1753.23 1576.63,1740.14 1614,1740.14 1618,1736.14 v3(1618,1732) ; U10.C5@1854.29,1190.71 v3(1869.85,1175.15)
  L4_SIG w4: v2(1837.53,722.62) 1837.53,736.55 1854.98,754 1861,754 1865,750 1865,740 1855,730 1855,719 1860,714 1906,714 1911,709 1911,704 1916,699 1925,699 1930,704 1930,730 1925,735 1899.98,735 1895,739.98 1895,747.02 1899.98,752 1924,752 1931,759 1931,785 1936,790 1980,790 1985,795 1985,872 1981,876 1943,876 1939,880 1939,888 1943,892 1977.31,892 1982,896.69 1982,903.31 1977.31,908 1943,908 1939,912 1939,920 1943,924 1978.31,924 1983,928.69 1983,935.31 1978.31,940 1943,940 1939,944 1939,952 1943,956 1979,956 1984,961 1984,969 1979,974 1963,974 1958,979 1958,1040 1939,1059 1939,1064.02 ; v3(1869.85,1175.15) 1879,1175.15 1884,1170.15 1884,1134 1889,1129 1934,1129 1939,1124 1939,1073.98 ; 1938.99,1064.03 1938.99,1073.97
  BOTTOM w5: v3(1618,1732) 1614,1728 1604,1728 1600,1732 1600,1768 1589,1779 1577,1779 1572,1784 1572,1798 1567,1803 1556,1803 1551,1798 1551,1770 1556,1765 1582,1765 1587,1760 1587,1740 1577,1730 1577,1719 1582,1714 1624.17,1714 1632.92,1705.25 1640,1690.25 1672,1622.46 1672,1609.2 1693.7,1587.5 1720.28,1587.5 1900,1407.78 1900,1278.77 1875.97,1180.15 1875,1180.15 1870,1175.15 v3(1869.85,1175.15) ; CN17.17@1831.77,690.09 1831.77,713.77 1837.53,719.53 v2(1837.53,722.62)
LCD_PSRAM_D2: CN17.16 U8.B12 U10.C6 | length 2164.5
  TOP w5: U8.B12@1512.36,1983.54 1512.46,1983.54 v3(1525.14,1970.86) ; U10.C6@1854.29,1161.18 1854.82,1161.18 1868,1148 v3(1869,1148)
  L4_SIG w4: v2(1817.48,630) 1826,638.52 1826,679 1831,684 1897.02,684 1902,688.98 1902,696.02 1897.02,701 1825.53,701 1820.53,706 1820.53,736.53 1850,766 1913.08,766 1918,770.92 1918,781 1913,786 1858,786 1853,791 1853,800 1858,805 1965,805 1970,810 1970,820 1965,825 1951,825 1946,830 1946,840 1951,845 1967,845 1972,850 1972,859 1967,864 1931,864 1926,869 1926,958.83 1942,974.83 1942,1038 1926,1054 1926,1111 1921,1116 1877,1116 1872,1121 1872,1145 v3(1869,1148)
  BOTTOM w5: v3(1525.14,1970.86) 1508.24,1947.28 1501,1927 1501,1880 1536,1845 1562.66,1827.8 1588.5,1803.5 1627.26,1751.16 1629.88,1747.34 1687,1631.22 1687,1631 1687.01,1626.79 1687,1615.42 1699.92,1602.5 1726.5,1602.5 1915,1414 1915,1304 1906.27,1256.87 1886.09,1173.36 1880.25,1162.74 v3(1869,1148) ; v2(1817.48,630) 1817.48,625 1819.96,622.52 CN17.16@1819.96,575.91
LCD_PSRAM_D3: CN17.15 U8.C12 U10.D5 | length 2160.4
  TOP w4: U10.D5@1824.76,1190.71 1840,1165 1840,1155 v3@1848.68,1140
  TOP w5: U8.C12@1512.36,1957.95 1525,1945.31 1525,1945.18 v3(1525.09,1945.09) ; v3@1848.68,1140 v3(1851,1136)
  L4_SIG w4: v2(1809,659.09) 1808.53,659.56 1808.53,741.53 1841,774 1841,815 1846,820 1928.31,820 1933,824.69 1933,831.31 1928.31,836 1846,836 1841,841 1841,847 1846,852 1908,852 1913,857 1913,969 1908,974 1857,974 1852,979 1852,1015 1857,1020 1909,1020 1914,1025 1914,1065 1910,1069 1850.69,1069 1846,1073.69 1846,1080.31 1850.69,1085 1910,1085 1914,1089 1914,1098 1909,1103 1851,1103 1846,1108 1846,1131 v3(1851,1136)
  BOTTOM w5: v3(1525.09,1945.09) 1510,1923.35 1510,1885 1543.05,1851.95 1570.61,1836.39 1595.5,1814.5 1601,1809 1635.82,1761.38 1663.37,1719.33 1680.7,1689.09 1729.37,1629.32 1753.5,1597.5 1930,1421 1930,1310 1919.99,1257.08 1899.06,1171.52 1889.5,1154.5 1886.75,1148.25 1884,1140 1879.5,1135.5 1871,1133.12 1862.76,1133.06 v3(1851,1136) ; CN17.15@1808.15,690.09 1808.15,659.94 v2(1809,659.09)
LCD_PSRAM_D4: CN17.14 U8.R8 U10.E5 | length 2071.6
  TOP w5: U8.R8@1410,1650.87 1410,1581 1415,1576 1421,1576 1426,1581 v3(1426,1584) ; v3(1782.71,1175.48) 1782.71,1178.18 U10.E5@1795.24,1190.71
  L4_SIG w4: v3(1782.71,1175.48) 1828,1175.48 1833,1170.48 1833,1059 1838,1054 1897,1054 1902,1049 1902,1037 1897,1032 1840,1032 1835,1027 1835,964 1840,959 1895,959 1900,954 1900,946 1896,942 1861.69,942 1857,937.31 1857,930.69 1861.69,926 1896,926 1900,922 1900,914 1896,910 1834.69,910 1830,905.31 1830,898.69 1834.69,894 1896,894 1900,890 1900,882 1896,878 1834,878 1829,873 1829,779 1792,742 v2(1792,630)
  BOTTOM w5: v3(1426,1584) 1433,1584 1437,1580 1437,1534 1433,1530 1433,1475 1439,1469 1471,1469 1476,1474 1476,1492 1481,1497 1498.78,1497 1511.21,1497.01 1511.56,1497 1535.56,1473 1568.68,1473 1594.68,1447 1610.46,1447 1675,1382.46 1675,1338.22 1675.01,1338.06 1683.79,1329.28 1683.94,1329.28 1690.01,1323.21 1690.01,1323.05 1703.71,1309.35 1726.91,1309.35 1735,1301.26 1735,1300.98 1735.12,1300.86 1735.12,1292.88 1740,1288 1753,1288 1758,1283 1758,1271 1753,1266 1739,1266 1734,1261 1734,1251 1739,1246 1790,1246 1795,1241 1795,1230 1790,1225 1769.5,1225 1764.5,1220 1764.5,1164 1769.5,1159 1777.71,1159 1782.71,1164 v3(1782.71,1175.48) ; v2(1792,630) 1796.34,625.66 CN17.14@1796.34,575.91
LCD_PSRAM_D5: CN17.13 U8.P8 U10.F5 | length 2067.9
  TOP w5: U8.P8@1410,1676.46 1397,1663.46 1397,1642.59 1396.5,1642.09 1396.5,1612.72 1395,1611.22 1395,1554 1400,1549 1416.5,1549 1421.5,1554 v3(1421.5,1560) ; v3(1750,1205) 1764.29,1190.71 U10.F5@1765.71,1190.71
  L4_SIG w4: v3(1750,1205) 1750,1215 1755,1220 1896,1220 1901,1215 1901,1195 1896,1190 1773,1190 1768,1185 1768,1164.62 1773,1159.62 1816,1159.62 1821,1154.62 1821,968 1816,963 1787,963 1782,958 1782,948 1787,943 1840.02,943 1845,938.02 1845,930.98 1840.02,926 1821,926 1816,921 1816,840 1811,835 1787,835 1783,831 1783,823 1787,819 1810,819 1815,814 1815,806 1810,801 1785,801 1780,796 1780,787 1785,782 1797,782 1802,777 1802,769 1797,764 1785,764 1780,759 1780,728 1775,723 v2(1769.53,723)
  BOTTOM w5: v3(1421.5,1560) 1418,1556.5 1418,1465.44 1429.44,1454 1486,1454 1491,1459 1491,1477 1496,1482 1505,1482 1510,1477 1510,1425 1515,1420 1528,1420 1533,1425 1533,1453 1538,1458 1561.46,1458 1587.46,1432 1604.24,1432 1660,1376.24 1660,1332 1720,1272 1720,1240 1725,1235 1742,1235 1747,1230 1747,1224 1742,1219 1726,1219 1721,1214 1721,1197 1726,1192 1745,1192 1750,1197 v3(1750,1205) ; v2(1769.53,723) 1784.53,708 CN17.13@1784.53,690.09
LCD_PSRAM_D6: CN17.12 U8.P9 U10.F6 | length 1944.1
  TOP w5: v3(1425.09,1631) 1423.09,1633 1423.09,1663.96 U8.P9@1435.59,1676.46 ; v3(1744,1143.5) 1744,1065 1749,1060 1758,1060 1763,1065 1763,1113 1760,1116 1760,1155.47 U10.F6@1765.71,1161.18
  L4_SIG w4: v3(1744,1143.5) 1741,1140.5 1741,1128 1746,1123 1755.02,1123 1760,1118.02 1760,1110.98 1755.02,1106 1746,1106 1741,1101 1741,1093 1746,1088 1755,1088 1758,1085 1758,928 1753,923 1717,923 1712,918 1712,909 1716,905 1754,905 1758,901 1758,893 1754,889 1716,889 1712,885 1712,877 1716,873 1754,873 1758,869 1758,861 1754,857 1716,857 1712,853 1712,845 1716,841 1754,841 1758,837 1758,829 1754,825 1716,825 1712,821 1712,724 1730,706 1774,706 1779,701 1779,659 v2(1775,655)
  BOTTOM w5: v3(1425.09,1631) 1425.09,1629.6 1410.5,1615.01 1410.5,1613.94 1388,1591.44 1388,1453 1417.01,1423.99 1454.23,1423.99 1498.22,1380 1508.78,1380 1521.21,1380.01 1542.22,1359 1577,1359 1613,1323 1626.56,1323 1700,1249.56 1700,1146.5 1705,1141.5 1742,1141.5 v3(1744,1143.5) ; CN17.12@1772.72,575.91 1772.72,636.72 1775,639 v2(1775,655)
LCD_PSRAM_D7: CN17.11 U8.R9 U10.G6 | length 2131.4
  TOP w5: v3(1425,1609) 1439.68,1623.68 1439.68,1646.78 U8.R9@1435.59,1650.87 ; U10.G6@1736.18,1161.18 1750,1175 v3(1750,1176.74)
  L4_SIG w4: v2(1742,723) 1730,723 1725,728 1725,736 1730,741 1760,741 1765,746 1765,755 1760,760 1730,760 1725,765 1725,772 1730,777 1761.02,777 1766,781.98 1766,789.02 1761.02,794 1728.98,794 1724,798.98 1724,806.02 1728.98,811 1765,811 1770,816 1770,824.02 ; v3(1750,1176.74) 1750,1165 1760,1155 1760,1138 1769,1129 1803,1129 1808,1124 1808,1113 1803,1108 1774.69,1108 1770,1103.31 1770,1096.69 1774.69,1092 1804.31,1092 1809,1087.31 1809,1080.69 1804.31,1076 1776.69,1076 1772,1071.31 1772,1064.69 1776.69,1060 1804.31,1060 1809,1055.31 1809,1048.69 1804.31,1044 1776,1044 1771,1039 1771,1000 1776,995 1804.31,995 1809,990.31 1809,983.69 1804.31,979 1774,979 1770,975 1770,935 1774,931 1796.31,931 1801,926.31 1801,919.69 1796.31,915 1774,915 1770,911 1770,903 1774,899 1797.31,899 1802,894.31 1802,887.69 1797.31,883 1774,883 1770,879 1770,871 1774,867 1797.31,867 1802,862.31 1802,855.69 1797.31,851 1774,851 1770,847 1770,833.98 ; 1770.01,824.03 1770.01,833.97
  BOTTOM w5: v3(1425,1609) 1425,1605 1403,1583 1403,1459.22 1423.22,1439 1490,1439 1495,1434 1495,1410 1500,1405 1521,1405 1526,1400 1526,1396.44 1532.44,1390 1544,1390 1549,1395 1549,1428 1554,1433 1565.24,1433 1571,1427.24 1571,1380 1576,1375 1584,1375 1589,1380 1589,1406 1594,1411 1602.01,1411 1607.01,1406 1607.01,1352 1612.01,1347 1621,1347 1626,1352 1626,1369 1631,1374 1640,1374 1645,1369 1645,1338.22 1644.99,1325.79 1711,1259.78 1711,1159 1716,1154 1727,1154 1732,1159 1732,1171.74 1737,1176.74 v3(1750,1176.74) ; v2(1742,723) 1760.91,704.09 CN17.11@1760.91,690.09
LCD_PSRAM_D8: CN17.10 U8.P10 U10.B1 | length 2067
  TOP w5: U8.P10@1461.18,1676.46 1448.68,1663.96 1448.68,1619.95 1444,1615.27 1444,1552.25 1448.75,1547.5 1471.64,1547.5 1482.5,1558.36 v3(1482.5,1564) ; U10.B1@1883.82,1308.82 1883.82,1323.82 1931.96,1371.96 1931.96,1379.04 1925.54,1385.46 1918.46,1385.46 1890.36,1357.36 v3(1884.5,1357.36)
  L4_SIG w4: v2(1742.49,544.95) 1826.95,544.95 1998,716 1998,748 2003.98,753.98 2022,772.02 2022,1109 2020.85,1110.15 2020.78,1110.15 2012,1118.93 2012,1119 1996,1135 1996,1237 1884.5,1348.5 v3(1884.5,1357.36)
  BOTTOM w5: v3(1482.5,1564) 1482.5,1565 1487.5,1570 1507.65,1570 1519.65,1558 1564.79,1558 1574.13,1548.66 1574.13,1523.22 1577.55,1519.8 1585.54,1519.8 1613.34,1492 1647.53,1492 1670,1469.53 1670,1451.12 1720,1401.12 1720,1358.78 ; 1720.01,1358.77 1720.01,1356.34 1747.08,1329.27 1815.73,1329.27 1821,1324 1821,1281 1826,1276 1849.5,1276 1854.5,1281 1854.5,1302.58 1884.5,1332.58 v3(1884.5,1357.36) ; v2(1742.49,544.95) 1749.09,551.55 CN17.10@1749.09,575.91
LCD_PSRAM_D9: CN17.9 U8.R10 U10.C1 | length 1904
  TOP w5: U8.R10@1461.18,1650.87 1457.68,1647.37 1457.68,1612.54 1459,1611.22 1459,1591 1465,1585 v3(1482.5,1585) ; v3(1839,1354) 1839,1341.69 1843.69,1337 1850.31,1337 1855,1341.69 1855,1372 1872,1389 1872,1420 1877,1425 1885,1425 1890,1420 1890,1379 1885,1374 1878,1374 1869,1365 1869,1313.82 1864,1308.82 U10.C1@1854.29,1308.82
  L4_SIG w4: v2(1689,609) 1697,617 1697.05,617 1723,642.95 1723,674 1687,710 1687,979 1692,984 1726,984 1731,989 1731,1068 1717,1082 1717,1221 1761,1265 1761,1297 1818,1354 v3(1839,1354)
  BOTTOM w5: v3(1482.5,1585) 1483.5,1586 1530.22,1586 1534.69,1590.47 1555.92,1590.47 1589.13,1557.26 1589.13,1537.43 1619.56,1507 1653.75,1507 1685,1475.75 1685,1457.34 1735,1407.34 1735,1365 1735.01,1362.56 1757.57,1340 1826.1,1340 1828,1338.1 1849,1338.1 1854,1343.1 1854,1353 1849,1358 1843,1358 v3(1839,1354) ; v2(1689,609) 1691,609 1729,647 1729,670 1737.28,678.28 CN17.9@1737.28,690.09
LCD_PSRAM_D10: CN17.8 U8.N11 U10.C2 | length 2042
  TOP w5: v3(1474.04,1689.32) U8.N11@1486.77,1702.05 ; U10.C2@1854.29,1279.29 1868.58,1293.58 v3(1869,1293.58)
  L4_SIG w4: v2(1749,619) 1749,602 1756,595 1860,595 1958.5,693.5 1958.5,761 1963.5,766 1999,766 2010,777 2010,996 2005,1001 1990,1001 1985,1006 1985,1051.86 1990,1056.86 2006,1056.86 2010,1060.86 2010,1068.86 2006,1072.86 1968,1072.86 1964,1076.86 1964,1110 1969,1115 1979,1115 1984,1120 1984,1232 1922.42,1293.58 v3(1869,1293.58)
  BOTTOM w5: v3(1474.04,1689.32) 1474.04,1696 1479.04,1701 1494,1701 1499,1696 1499,1677 1494,1672 1454,1672 1449,1667 1449,1613 1452,1610 1452,1548.58 1487.58,1513 1487.8,1512.8 1516.98,1512.8 1541.78,1488 1574.9,1488 1600.9,1462 1616.68,1462 1690,1388.68 1690,1346.34 1690.01,1343.9 1714.41,1319.5 1729.5,1319.5 1746,1303 1762,1303 1765.18,1299.82 1765.18,1288.84 1774,1280.02 1774,1265 1779,1260 1879,1260 1884,1265 1884,1288.58 1879,1293.58 v3(1869,1293.58) ; CN17.8@1725.47,575.91 1725.47,596.47 1748,619 v2(1749,619)
LCD_PSRAM_D11: CN17.7 U8.P11 U10.D2 | length 2072.4
  TOP w5: v3(1482.1,1606.05) 1476.95,1606.05 1466.68,1616.32 1466.68,1638.69 1473.68,1645.69 1473.68,1663.37 U8.P11@1486.77,1676.46 ; U10.D2@1824.76,1279.29 1838.97,1293.5 v3(1840,1293.5)
  L4_SIG w4: v2(1690,634) 1708,652 1708,670 1675,703 1675,992 1680,997 1713.31,997 1718,1001.69 1718,1010 1713,1015 1684,1015 1679,1020 1679,1028 1684,1033 1714,1033 1719,1038 1719,1063 1714,1068 1682,1068 1677,1073 1677,1154 1682,1159 1700,1159 1705,1164 1705,1229 1746,1270 1746,1299 1818,1371 1845,1371 1856,1360 1856,1311.34 1840,1295.34 v3(1840,1293.5)
  BOTTOM w5: v3(1482.1,1606.05) 1487.15,1601 1554.51,1601 1565.23,1611.72 1565.23,1637.33 1570.23,1642.33 1583.23,1642.33 1586.95,1638.61 1586.95,1601.77 1587.23,1601.49 1587.23,1586.41 1612,1561.64 1612,1535.78 1625.78,1522 1664.31,1522 1669.8,1527.49 1691.51,1527.49 1700,1519 1700,1463.56 1750,1413.56 1750,1368.79 1763.79,1355 1818.78,1355 1837.77,1373.99 1841.21,1373.99 1854.97,1374 1859.97,1379 1859.97,1392.75 1869.61,1402.39 1876.7,1402.39 1881.7,1397.39 1881.7,1376.7 1869,1364 1869,1333.71 1840,1304.71 v3(1840,1293.5) ; v2(1690,634) 1692,634 1713.66,655.66 CN17.7@1713.66,690.09
LCD_PSRAM_D12: CN17.6 U8.R11 U10.E2 | length 2051.3
  TOP w5: v3(1481.35,1627.04) 1486.77,1632.46 U8.R11@1486.77,1650.87 ; v3(1779.68,1294.85) U10.E2@1795.24,1279.29
  L4_SIG w4: v2(1749,655) 1741,655 1736,660 1736,669 1741,674 1760,674 1765,679 1765,689 1760,694 1724,694 1699,719 1699,931 1704,936 1741,936 1746,941 1746,949 1741,954 1704,954 1699,959 1699,967 1704,972 1739,972 1744,977 1744,1072 1729,1087 1729,1213 1757,1241 1792,1241 1797,1246 1797,1255 1792,1260 1778.98,1260 1774,1264.98 1774,1272.02 1778.98,1277 1818,1277 1823,1282 1823,1316 1818,1321 1809,1321 1804,1316 1804,1299.85 1799,1294.85 v3(1779.68,1294.85)
  BOTTOM w5: v3(1481.35,1627.04) 1481.35,1642 1486.35,1647 1498,1647 1503,1642 1503,1619 1508,1614 1518,1614 1523,1619 1523,1656.55 1518,1661.55 1467,1661.55 1462,1656.55 1462,1620 1467,1615 1467,1554.8 1494,1527.8 1523.2,1527.8 1548,1503 1581.12,1503 1607.12,1477 1641.31,1477 1655,1463.31 1655,1444.9 1705,1394.9 1705,1350.13 1725.86,1329.27 1733.73,1329.27 1748,1315 1803,1315 1809,1309 1809,1275 1804,1270 1794,1270 1789,1275 1789,1289.85 1784,1294.85 v3(1779.68,1294.85) ; CN17.6@1701.85,575.91 1701.85,596.85 1749,644 v2(1749,655)
LCD_PSRAM_D13: CN17.5 U8.P15 U10.F2 | length 1837.2
  TOP w5: U8.P15@1589.13,1676.46 1592.63,1672.96 1597.45,1672.96 1610.7,1659.71 1668.69,1659.71 1672.53,1655.87 1672.53,1602.84 1668.69,1599 1658.61,1599 1653.61,1604 1653.61,1643 1648.61,1648 1635,1648 1630,1643 v3(1630,1641) ; U10.F2@1765.71,1279.29 1756,1279.29 1751,1284.29 1751,1330 1746,1335 1736,1335 1731,1340 1731,1438 1735,1442 1747,1442 1752,1437 1752,1398 1757,1393 v3(1781,1393)
  L4_SIG w4: v2(1690.04,659) 1690.04,667.96 1662,696 1662,1027.78 1664,1029.78 1664,1166 1669,1171 1691,1171 1696,1176 1696,1236 1735,1275 1735,1306 1798,1369 1798,1385 1790,1393 v3(1781,1393)
  BOTTOM w5: v3(1630,1641) 1643,1641 1649.93,1634.07 1657,1619.09 1657,1602.98 1687.48,1572.5 1714.06,1572.5 1767,1519.56 1767,1479 1767.18,1478.82 1767.18,1478.43 1777.43,1468.18 1777.82,1468.18 1778,1468 1818.56,1468 1849,1437.56 1849,1403 1819,1373 1803,1373 1783,1393 v3(1781,1393) ; v2(1690.04,659) CN17.5@1690.04,690.09
LCD_PSRAM_D14: CN17.4 U8.P14 U10.F1 | length 1877.4
  TOP w5: v3(1550.74,1663.54) 1550.74,1663.66 U8.P14@1563.54,1676.46 ; U10.F1@1765.71,1308.82 1765.71,1330 1770.71,1335 1785,1335 1790,1340 1790,1350 1785,1355 1751,1355 1746,1360 1746,1368 1750,1372 v3(1780,1372)
  L4_SIG w4: v2(1676,544) 1659,561 1659,626 1663,630 1663,673 1658,678 1638,678 1633,683 1633,692 1637,696 1643.31,696 1648.31,701 1648.31,707 1643.31,712 1637,712 1633,716 1633,1043 1651,1061 1651,1180 1676,1205 1676,1247 1701,1272 1701,1298 1775,1372 v3(1780,1372)
  BOTTOM w5: v3(1550.74,1663.54) 1550.74,1663 1557.74,1656 1578,1656 1587,1665 1587,1677 1581,1683 1545.98,1683 1541,1687.98 1541,1695.02 1545.98,1700 1594.99,1700 1599.5,1695.49 1599.5,1685.49 1607.99,1677 1608,1667.01 1603.34,1662.35 1603.34,1592.31 1627,1568.65 1627,1542 1632,1537 1658.09,1537 1663.58,1542.49 1701.63,1542.49 1715,1529.12 1715,1469.78 1734.78,1450 1753.17,1450 1764.99,1438.18 1765.38,1438.18 1765.56,1438 1806.12,1438 1812,1432.12 1812,1425 1807,1420 1770,1420 1765.01,1415.01 1765.01,1375 1770.01,1370 1778,1370 v3(1780,1372) ; v2(1676,544) 1678.23,546.23 CN17.4@1678.23,575.91
LCD_PSRAM_D15: CN17.3 U8.N15 U10.G1 | length 1883.9
  TOP w5: U8.N15@1589.13,1702.05 1593.95,1702.05 1602,1694 1611.65,1694 1614,1691.65 v3(1614,1691.5) ; U10.G1@1736.18,1308.82 1716,1329 1716,1456 1721,1461 1764,1461 1769,1456 1769,1419 1774,1414 1782,1414 1787,1419 1787,1452 1792,1457 1802,1457 1807,1452 1807,1406 v3(1805,1404)
  L4_SIG w4: v2(1642,626) 1629,639 1621,656 1621,1050 1641.02,1206.64 1653.25,1247.5 1675,1284.13 1699.78,1325.86 1716.3,1344.28 1760,1393 1766,1399 1766,1399.22 1774.78,1408 1801,1408 v3(1805,1404)
  BOTTOM w5: v3(1614,1691.5) 1621,1691.5 1624.45,1688.05 1631.63,1672.83 1631.63,1664.63 1627,1660 1619,1660 1614,1655 1614,1633 1621.5,1625.5 1633.5,1625.5 1640.84,1618.16 1641.73,1616.27 1642,1615.7 1642,1583 1646,1579 1659.76,1579 1671.38,1567.38 1671.38,1562.62 1676.51,1557.49 1693.69,1557.49 1707.84,1557.5 1730,1535.34 1730,1527 1736,1521 1744.34,1521 1750,1515.34 1750,1508 1745,1503 1735,1503 1730,1498 1730,1476 1741,1465 1759.39,1465 1771.21,1453.18 1771.6,1453.18 1771.78,1453 1812.34,1453 1834,1431.34 1834,1409.22 1816.78,1392 1809,1392 1805,1396 v3(1805,1404) ; v2(1642,626) 1642,626.42 1666.42,650.84 CN17.3@1666.42,690.09
LCD_PSRAM_NOE: CN17.19 U8.D10 U10.A2 | length 2232.9
  TOP w5: v3(1447,1917) 1447,1918.18 U8.D10@1461.18,1932.36 ; U10.A2@1913.35,1279.29 1913.35,1281.35 v3(1966,1334)
  L4_SIG w4: v3(1447,1917) 1447,1916.91 1433,1902.91 1433,1684.75 1447.75,1670 1490,1670 1530,1630 1575.93,1630 1598.73,1607.2 1598.73,1554.65 1628,1525.38 1628,1525.28 1629.49,1523.79 1629.49,1469.49 1633.98,1465 1705.41,1465 1709.41,1469 1709.41,1484.17 1714.1,1488.86 1720.72,1488.86 1725.41,1484.17 1725.41,1469 1729.41,1465 1809.46,1465 1813.46,1469 1813.46,1473.31 1818.15,1478 1824.77,1478 1829.46,1473.31 1829.46,1469 1833.46,1465 1866.98,1465 1885.98,1446 1971,1446 2020,1397 2020,1346 2015,1341 1971,1341 1966,1336 v3(1966,1334) 1966,1318 2055,1229 2055,755 2050,750 2049.95,750 2040,740.05 2040,740 2039,739 2039,714 v2(2035,710)
  BOTTOM w5: CN17.19@1855.39,690.09 1855.39,679.61 1916,619 2001.03,619 2045,662.97 2045,700 v2(2035,710)
LCD_PSRAM_NWE: CN17.20 R64.1 U8.C11 | length 2255.5
  TOP w5: v3(1474.04,1970.68) U8.C11@1486.77,1957.95 ; v2(1845,659.74) 1845,665 1810,700 1810,766.02 1735,841.02 R64.1@1735,919.49 1925,880 2047,880 2082,915 2082,1578 2070,1590 v2(2048,1590)
  L4_SIG w4: v3(1474.04,1970.68) 1482.86,1961.86 1499,1931 1499,1882 1539,1842 1560.5,1829.5 1591.09,1798.91 1788.09,1798.91 1888,1699 1946,1699 2048,1597 v2(2048,1590)
  BOTTOM w5: v2(1845,659.74) 1850.26,659.74 1865,645 1865,578.12 CN17.20@1867.21,575.91
LCD_RST: CN17.23 R68.2 U8.N12 | length 1694.1
  TOP w5: U8.N12@1512.36,1702.05 v3(1525.22,1689.19) ; R68.2@2015,685 2015,715 2028,728 2052,728 v2(2057,733)
  L4_SIG w4: v3(1525.22,1689.19) 1528.41,1686 1559.27,1686 1586.99,1658.26 1625.36,1658.26 1626.36,1659.26 1647.63,1659.26 1676.04,1630.85 1676.04,1608.84 1761.88,1523 1830,1523 1894,1459 1976,1459 2045,1390 2045,1272 2067,1250 2067,743 v2(2057,733)
  BOTTOM w5: CN17.23@1902.64,690.09 1902.64,662.36 1931,634 1991.93,634 2016.56,658.63 2016.56,716.56 2028,728 2052,728 v2(2057,733)
LCD_TE_INT: CN17.2 U8.G14 | length 2518.7
  TOP w5: U8.G14@1563.54,1855.59 1576.04,1868.09 1593.72,1868.09 1595.72,1870.09 1613.14,1870.09 1637.73,1845.5 1641.43,1845.5 1655.93,1831 v3(1661,1831)
  L4_SIG w4: v2(2225,1615) 2235,1605 2235,1365 2260,1340 2260,940 2285,915 2285,620 v2(2260,595)
  BOTTOM w5: CN17.2@1654.61,575.91 1654.61,537.58 1665.69,526.5 1872.73,526.5 1889.23,510 1963.78,510 2003.78,550 2040,550 2085,595 v2(2260,595) ; v3(1661,1831) 1677,1815 1875,1815 1878,1812 1891.9,1812 1908.08,1811.98 2028,1812 v2(2225,1615)
LED_STLINK: R13.1 R14.1 U2.30 | length 890.2
  TOP w5: R13.1@1440,3500 R14.1@1500,3500 v2(1500,3230) ; v2(1865,3012.69) 1867.47,3015.16 U2.30@1966.26,3015.16
  L4_SIG w4: v2(1500,3230) 1500,3225 1650,3075 1715,3075 1760,3030 1847.69,3030 v2(1865,3012.69)
LEDA: CN17.28 L8.2 | length 1045
  TOP w5: L8.2@1100,465 v2(1135,465)
  L4_SIG w4: v2(1135,465) 1156,486 1503,486 1544,445 1830,445 1895,510 1970,510 2000,540 v2(2000,580)
  BOTTOM w5: CN17.28@1961.69,575.91 1995.91,575.91 v2(2000,580)
LEDK: CN17.29 R66.2 U12.4 | length 1356.2
  TOP w5: U12.4@862.61,803.07 862.61,852.39 R66.2@850,865 879.54,894.54 v2(879.54,895)
  BOTTOM w5: v2(879.54,895) 880,895 910,865 970,865 1045,790 1397,790 1431.5,755.5 1989.5,755.5 1998,747 1998,723 1973.5,698.5 CN17.29@1973.5,690.09
MIC_VDD1: C29.2 SB5.1 TP1.1 U7.A7 | length 369.1
  TOP w5: 295,2543 SB5.1@295,2551.66
  TOP w9: 512,2379.37 U7.A7@536.1,2379.37
  TOP w20: 295,2543 TP1.1@295,2455 345,2455 C29.2@415,2385 488,2385 493.63,2379.37 512,2379.37
MIC_VDD2: C31.2 TP2.1 U7.B6 | length 311.8
  TOP w5: TP2.1@295,2365 300,2360 385,2360 C31.2@415,2330 424,2330 v2(452,2358) ; v4(549.48,2353.39) U7.B6@555.79,2359.69
  BOTTOM w5: v2(452,2358) 463,2347 510,2347 524,2333 535,2333 549.48,2347.48 v4(549.48,2353.39)
NC1: TP3.1 U8.B5 | length 322.8
  TOP w5: TP3.1@1310,2255 1285,2230 1285,2205.82 1287.5,2203.32 1287.5,2114.5 1276,2103 1276,2084.15 1287.15,2073 1305.93,2073 1320.73,2058.2 1320.73,2033.78 1320.14,2033.19 1320.14,1996.63 U8.B5@1333.23,1983.54
NC4: TP5.1 U8.B9 | length 171.6
  TOP w4: U8.B9@1435.59,1983.54 1448,1995.95 1448,2054
  TOP w5: 1448,2054 1448,2078.74 1460,2090.74 TP5.1@1460,2145
NC8: TP14.1 U8.D2 | length 333.8
  TOP w5: TP14.1@980,2050 1025,2005 1158.78,2005 1190.5,1973.28 1190.5,1958.57 1199.57,1949.5 1212.96,1949.5 1217.6,1944.86 1243.96,1944.86 U8.D2@1256.46,1932.36
NC10: TP8.1 U8.E4 | length 533.9
  TOP w5: v2(1012,2107) 1010,2109 1010,2160 1045,2195 TP8.1@1045,2210 ; U8.E4@1307.64,1906.77 1320.24,1919.37 v3(1320.75,1919.37)
  BOTTOM w5: v2(1012,2107) 1014,2105 1026.18,2105 1087.56,2043.62 1147.38,2043.62 1184,2007 1231,2007 1271.28,1966.72 1271.28,1948.33 1300.24,1919.37 v3(1320.75,1919.37)
NC11: TP13.1 U8.D1 | length 378.4
  TOP w5: TP13.1@910,2050 935,2050 965,2020 988.78,2020 1018.78,1990 1150,1990 1175.5,1964.5 1175.5,1949.5 1192.64,1932.36 U8.D1@1230.87,1932.36
NETB1_2: B1.2 B1.4 R89.2 R90.2 | length 300.7
  BOTTOM w5: B1.2@2873.53,1754.54 B1.4@3064.47,1754.54 3064.47,1695.53 R89.2@3065,1695 R90.2@3015,1695
NETB2_1: B2.1 B2.3 C87.2 R91.1 SB34.2 | length 311.2
  BOTTOM w5: B2.1@2873.53,1300.46 2906.19,1333.12 SB34.2@2906.19,1369.17 2907.02,1370 R91.1@3015,1370 C87.2@3065,1370 3065,1300.99 B2.3@3064.47,1300.46
NETC8_2: C8.2 U3.4 | length 68.8
  TOP w20: C8.2@2355,2935 2357.6,2932.4 U3.4@2422.76,2932.4
NETC9_2: C9.2 C10.2 SB7.2 U3.1 U3.3 | length 280.8
  TOP w20: U3.1@2517.24,2857.6 2570,2857.6 2582.4,2870 C10.2@2595,2870 ; U3.3@2517.24,2932.4 2582.6,2932.4 C9.2@2585,2930 2595,2920 C10.2@2595,2870 ; 2595,2805 C10.2@2595,2870
NETC18_1: C18.1 U7.B7 | length 249.7
  TOP w5: v4(549.49,2385.67) U7.B7@555.79,2379.37
  TOP w15: C18.1@420,2540 420,2529 475,2474 v2(475,2445)
  BOTTOM w10: v2(475,2445) 475,2405 495,2385 548.82,2385 v4(549.49,2385.67)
